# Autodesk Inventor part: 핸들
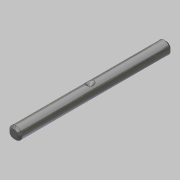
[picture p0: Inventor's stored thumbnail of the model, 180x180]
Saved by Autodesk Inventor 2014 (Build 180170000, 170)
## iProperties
Created: 2019-04
Part Number: 핸들
Material: 스테인리스강
Document SubType Name: Modeling
Designer: mduedu
Density: 1 g/cm^3
Appearance: 반광택
Author: mduedu
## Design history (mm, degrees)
sketch "스케치1"
  geometry: C1 r 3 at (0, 0); 1 further point
  constraints: 1 centre point, 1 coincident
  dimensions: "d0" = 6 diameter of C1
extrude "돌출1" new body sketch "스케치1" stored distance "d1" = 74; taper "d2" = 0 deg
chamfer "모따기1" distance "d3" = 1; stored, may be unused: second distance "d4" = 2, angle "d5" = 45 deg
sketch "스케치2"
  geometry: L1 (-36, 3)-(36, 3) reference; L2 (0, 3)-(0, 1); L3 (0, 1)-(2, 3); L4 (0, 3)-(2, 3); 1 further point
  constraints: 6 end point, 2 perpendicular, 1 midpoint, 1 point on line
  dimensions: "d6" = 4 diameter of L3.end L2; "d8" = 45 deg angle of L3 L2
revolve "회전1" sketch "스케치2" stored, may be unused: angle "d10" = 90 deg
node "작업점1"
  node "작업축1"
  node "작업 평면1"
node "솔리드1"
